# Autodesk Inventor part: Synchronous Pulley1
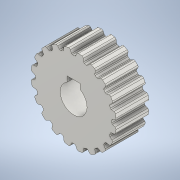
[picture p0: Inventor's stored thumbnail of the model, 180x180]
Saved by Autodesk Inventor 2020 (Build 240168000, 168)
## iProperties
CustomPartVersion: 1
Created: 2019-09
Part Number: Synchronous Pulley1
Material: Steel
Document SubType Name: Modeling
Designer: user
Density: 1 g/cm^3
Appearance: Steel
Author: user
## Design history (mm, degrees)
sketch "Pulley Sketch"
  geometry: L1 (-1.401, 15.854)-(-0.66, 14.265); L2 (-0.66, 14.265)-(0.66, 14.265); L3 (0.66, 14.265)-(1.401, 15.854); L4 (0, 0)-(0, 15.916); C1 r 16.17 at (0, 0); A1 r 15.916 centre (0, 0) between (-1.401, 15.854) and (1.401, 15.854); 2 further points
  constraints: 8 end point, 3 coincident, 3 point on circle, 2 centre point, 1 horizontal, 1 midpoint, 1 point on line, 1 vertical, 1 vertical alignment, 3 other
  dimensions: "d0" = 32.34028 diameter of C1 (computed from da_pb, da_z); "d1" = 0.254 radial gap between concentric circles of C1 A1 (= da_a); "d2" = 1.651 dimension on A1 (= da_hg); "d3" = 50 deg angle of L3 L1 (= 2 x da_fi); "d4" = 1.3208 distance of L1.end L2.end (= da_bw)
extrude "Base Body" new body sketch "Pulley Sketch" stored distance "d5" = 12.192 (= da_bf); taper "d6" = 0 deg
extrude "Tooth" cut sketch "Pulley Sketch" extent not by distance; stored distance "d7" = 12.192 (= da_bf); taper "d8" = 0 deg
fillet "Tooth Fillet" dims "d9" = 0.4064 (= da_rb), "d10" = 0.635 (= da_rt)
feature "Left flange"
feature "Right flange"
sketch "Sketch2"
  geometry: L1 (-2.416, 6.387)-(2.416, 6.387); L2 (2.416, 6.387)-(2.416, 4.378); L3 (-2.416, 4.378)-(-2.416, 6.387); A1 r 5 centre (0, 0) between (-2.416, 4.378) and (2.416, 4.378); 2 further points
  constraints: 6 end point, 2 point on circle, 1 centre point, 1 coincident, 1 horizontal, 1 midpoint, 1 parallel, 1 perpendicular, 1 vertical alignment
  dimensions: "d17" = 10 diameter of A1
extrude "Extrusion3" cut sketch "Sketch2" extent not by distance; stored distance "d18" = 0; taper "d19" = 0 deg
body "Solid1"
pattern_circular "Teeth" dims angle "d12" = 360 deg
other parameters: "da_pb" = 5.08 [user parameter; used in 1 equation term], "da_fi" = 25 deg [user parameter; used in 1 equation term], "da_hg" = 1.651 [user parameter; used in 1 equation term], "da_bw" = 1.3208 [user parameter; used in 1 equation term], "da_rb" = 0.4064 [user parameter; used in 1 equation term], "da_rt" = 0.635 [user parameter; used in 1 equation term], "da_a" = 0.254 [user parameter; used in 3 equation terms], "da_bf" = 12.192 [user parameter; used in 2 equation terms], "d15" = 0, "da_wf" = 1.5 [user parameter; used in 2 equation terms], "da_hf" = 1.5 [user parameter; used in 2 equation terms], "d16" = 0
